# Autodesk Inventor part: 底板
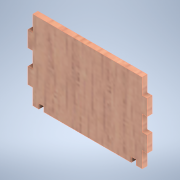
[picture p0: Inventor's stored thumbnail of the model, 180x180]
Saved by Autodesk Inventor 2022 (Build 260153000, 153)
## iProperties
Created: 2024-11
Part Number: 底板
Material: 木 (オーク)
Document SubType Name: Modeling
Designer: shimizu
Density: 0.76 g/cm^3
Appearance: ホワイト オーク材 - ナチュラル 標準の光沢
Author: shimizu
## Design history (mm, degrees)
sketch "スケッチ1"
  geometry: L1 (-25.119, 10.226)-(29.881, 10.226); L2 (29.881, -29.774)-(-25.119, -29.774); L3 (-25.119, 2.226)-(-27.619, 2.226); L4 (-27.619, 2.226)-(-27.619, -5.774); L5 (-27.619, -5.774)-(-25.119, -5.774); L6 (-25.119, -13.774)-(-27.619, -13.774); L7 (-27.619, -13.774)-(-27.619, -21.774); L8 (-27.619, -21.774)-(-25.119, -21.774); L9 (29.881, 2.226)-(32.381, 2.226); L10 (32.381, 2.226)-(32.381, -5.774); L11 (32.381, -5.774)-(29.881, -5.774); L12 (29.881, -13.774)-(32.381, -13.774); L13 (32.381, -13.774)-(32.381, -21.774); L14 (32.381, -21.774)-(29.881, -21.774); L15 (-25.119, 2.226)-(-25.119, 10.226); L16 (-25.119, -29.774)-(-25.119, -21.774); L17 (-25.119, -13.774)-(-25.119, -5.774); L18 (29.881, 10.226)-(29.881, 2.226); L19 (29.881, -5.774)-(29.881, -13.774); L20 (29.881, -21.774)-(29.881, -29.774); L21 (-22.119, -29.774)-(-19.619, -29.774); L22 (-19.619, -29.774)-(-19.619, -27.274); L23 (-19.619, -27.274)-(-22.119, -27.274); L24 (-22.119, -27.274)-(-22.119, -29.774); L25 (24.381, -27.274)-(26.881, -27.274); L26 (26.881, -27.274)-(26.881, -29.774); L27 (26.881, -29.774)-(24.381, -29.774); L28 (24.381, -29.774)-(24.381, -27.274); 3 further points
  constraints: 56 end point, 20 parallel, 9 perpendicular, 7 horizontal, 4 collinear, 2 point on line
  dimensions: "d16" = 60 distance between parallel lines of L13 L7; "d17" = 2.5 distance between parallel lines of L22 L24; "d18" = 2.5 distance between parallel lines of L2 L23; "d19" = 3 distance between parallel lines of L16 L24; "d20" = 2.5 distance of L25.start L25.end; "d21" = 2.5 distance of L25.end L26.end; "d22" = 3 distance between parallel lines of L20 L26; "d23" = 2.5 distance of L9.start L9.end; "d24" = 2.5 distance of L3.start L3.end
extrude "押し出し1" new body sketch "スケッチ1" distance "d2" = 2.5; taper "d3" = 0 deg
node "ソリッド1"
